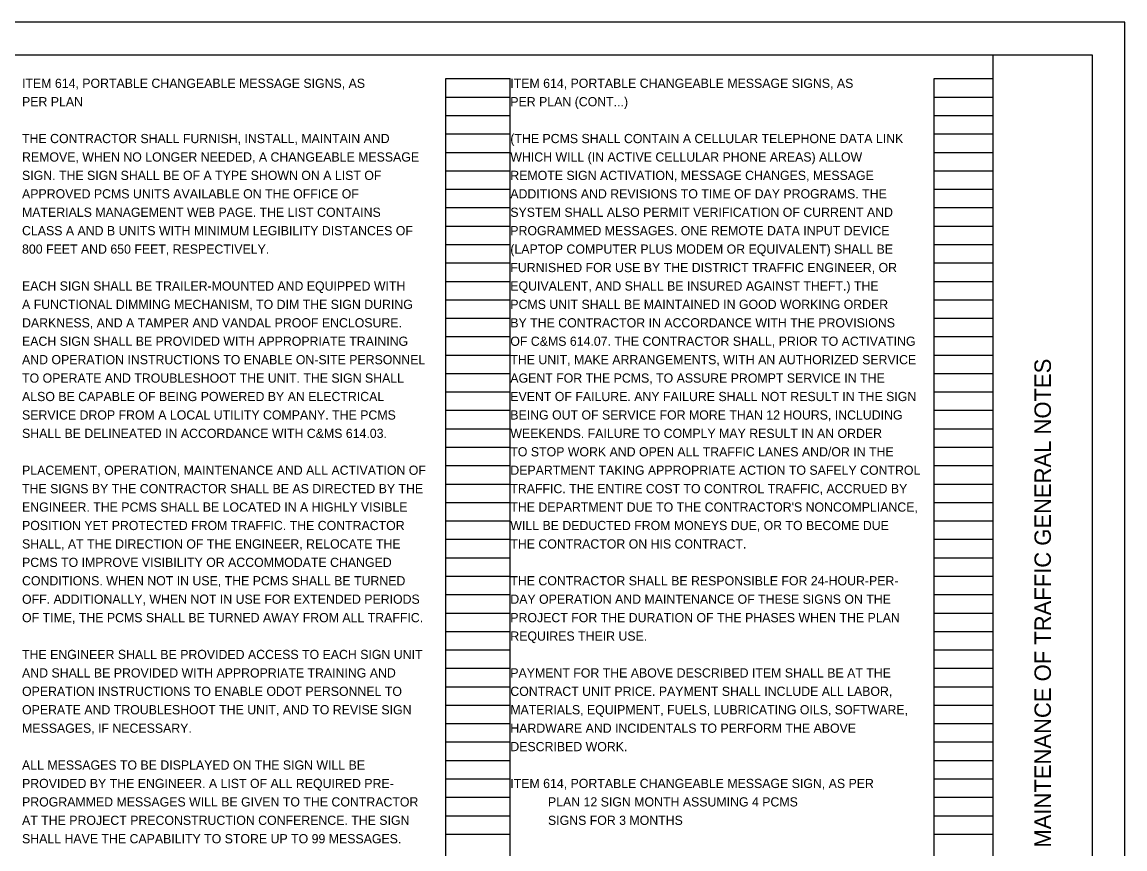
# Model space of a CAD drawing. Extents: x 0 to 34, y 0 to 22.
# Drawn here: x 17.24 to 34, y 9.43 to 22 of the extents above; entities that cross this region are included whole.
import ezdxf

# ---------------------------------------------------------------- set-up
doc = ezdxf.new("R2010")
doc.units = 0
for name, color, linetype in [('SH_Border', 7, 'Continuous'), ('SH_Cut_Line', 7, 'Continuous'), ('SH_Data', 7, 'Continuous'), ('SH_Text', 7, 'Continuous')]:
    doc.layers.add(name, color=color, linetype=linetype)

msp = doc.modelspace()

# ---------------------------------------------------------------- linework, layer by layer
at = {"layer": 'SH_Border'}
msp.add_line((32, 0.5), (32, 21.5), dxfattribs=at)
msp.add_lwpolyline([(1.5, 21.5), (33.5, 21.5), (33.5, 0.5), (1.5, 0.5)], close=True, dxfattribs=at)
at = {"layer": 'SH_Cut_Line'}
msp.add_lwpolyline([(0, 0), (34, 0), (34, 22), (0, 22)], close=True, dxfattribs=at)
at = {"layer": 'SH_Data'}
for p, q in [((23.68, 0.98), (23.68, 21.14)), ((23.68, 21.14), (24.66, 21.14)), ((24.66, 0.98), (24.66, 21.14)), ((31.1, 0.98), (31.1, 21.14)), ((31.1, 21.14), (32, 21.14)), ((32, 0.98), (32, 21.14)), ((23.68, 20.86), (24.66, 20.86)), ((31.1, 20.86), (32, 20.86)), ((23.68, 20.58), (24.66, 20.58)), ((31.1, 20.58), (32, 20.58)), ((23.68, 20.3), (24.66, 20.3)), ((31.1, 20.3), (32, 20.3)), ((23.68, 20.02), (24.66, 20.02)), ((31.1, 20.02), (32, 20.02)), ((23.68, 19.74), (24.66, 19.74)), ((31.1, 19.74), (32, 19.74)), ((23.68, 19.46), (24.66, 19.46)), ((31.1, 19.46), (32, 19.46)), ((23.68, 19.18), (24.66, 19.18)), ((31.1, 19.18), (32, 19.18)), ((23.68, 18.9), (24.66, 18.9)), ((31.1, 18.9), (32, 18.9)), ((23.68, 18.62), (24.66, 18.62)), ((31.1, 18.62), (32, 18.62)), ((23.68, 18.34), (24.66, 18.34)), ((31.1, 18.34), (32, 18.34)), ((23.68, 18.06), (24.66, 18.06)), ((31.1, 18.06), (32, 18.06)), ((23.68, 17.78), (24.66, 17.78)), ((31.1, 17.78), (32, 17.78)), ((23.68, 17.5), (24.66, 17.5)), ((31.1, 17.5), (32, 17.5)), ((23.68, 17.22), (24.66, 17.22)), ((31.1, 17.22), (32, 17.22)), ((23.68, 16.94), (24.66, 16.94)), ((31.1, 16.94), (32, 16.94)), ((23.68, 16.66), (24.66, 16.66)), ((31.1, 16.66), (32, 16.66)), ((23.68, 16.38), (24.66, 16.38)), ((31.1, 16.38), (32, 16.38)), ((23.68, 16.1), (24.66, 16.1)), ((31.1, 16.1), (32, 16.1)), ((23.68, 15.82), (24.66, 15.82)), ((31.1, 15.82), (32, 15.82)), ((23.68, 15.54), (24.66, 15.54)), ((31.1, 15.54), (32, 15.54)), ((23.68, 15.26), (24.66, 15.26)), ((31.1, 15.26), (32, 15.26)), ((23.68, 14.98), (24.66, 14.98)), ((31.1, 14.98), (32, 14.98)), ((23.68, 14.7), (24.66, 14.7)), ((31.1, 14.7), (32, 14.7)), ((23.68, 14.42), (24.66, 14.42)), ((31.1, 14.42), (32, 14.42)), ((23.68, 14.14), (24.66, 14.14)), ((31.1, 14.14), (32, 14.14)), ((23.68, 13.86), (24.66, 13.86)), ((31.1, 13.86), (32, 13.86)), ((23.68, 13.58), (24.66, 13.58)), ((31.1, 13.58), (32, 13.58)), ((23.68, 13.3), (24.66, 13.3)), ((31.1, 13.3), (32, 13.3)), ((23.68, 13.02), (24.66, 13.02)), ((31.1, 13.02), (32, 13.02)), ((23.68, 12.74), (24.66, 12.74)), ((31.1, 12.74), (32, 12.74)), ((23.68, 12.46), (24.66, 12.46)), ((31.1, 12.46), (32, 12.46)), ((23.68, 12.18), (24.66, 12.18)), ((31.1, 12.18), (32, 12.18)), ((23.68, 11.9), (24.66, 11.9)), ((31.1, 11.9), (32, 11.9)), ((23.68, 11.62), (24.66, 11.62)), ((31.1, 11.62), (32, 11.62)), ((23.68, 11.34), (24.66, 11.34)), ((31.1, 11.34), (32, 11.34)), ((23.68, 11.06), (24.66, 11.06)), ((31.1, 11.06), (32, 11.06)), ((23.68, 10.78), (24.66, 10.78)), ((31.1, 10.78), (32, 10.78)), ((23.68, 10.5), (24.66, 10.5)), ((31.1, 10.5), (32, 10.5)), ((23.68, 10.22), (24.66, 10.22)), ((31.1, 10.22), (32, 10.22)), ((23.68, 9.94), (24.66, 9.94)), ((31.1, 9.94), (32, 9.94)), ((23.68, 9.66), (24.66, 9.66)), ((31.1, 9.66), (32, 9.66))]:
    msp.add_line(p, q, dxfattribs=at)

# ---------------------------------------------------------------- texts
msp.add_text('MAINTENANCE OF TRAFFIC GENERAL NOTES', height=0.25, rotation=90, dxfattribs=at).set_placement((32.875, 9.455))
at = {"layer": 'SH_Text'}
for s, p in [('ITEM 614, PORTABLE CHANGEABLE MESSAGE SIGNS, AS', (17.24, 21)), ('ITEM 614, PORTABLE CHANGEABLE MESSAGE SIGNS, AS', (24.66, 21)), ('PER PLAN', (17.24, 20.72)), ('PER PLAN (CONT...)', (24.66, 20.72)), ('THE CONTRACTOR SHALL FURNISH, INSTALL, MAINTAIN AND', (17.24, 20.16)), ('(THE PCMS SHALL CONTAIN A CELLULAR TELEPHONE DATA LINK', (24.66, 20.16)), ('REMOVE, WHEN NO LONGER NEEDED, A CHANGEABLE MESSAGE', (17.24, 19.88)), ('WHICH WILL (IN ACTIVE CELLULAR PHONE AREAS) ALLOW', (24.66, 19.88)), ('SIGN. THE SIGN SHALL BE OF A TYPE SHOWN ON A LIST OF', (17.24, 19.6)), ('REMOTE SIGN ACTIVATION, MESSAGE CHANGES, MESSAGE', (24.66, 19.6)), ('APPROVED PCMS UNITS AVAILABLE ON THE OFFICE OF', (17.24, 19.32)), ('ADDITIONS AND REVISIONS TO TIME OF DAY PROGRAMS. THE', (24.66, 19.32)), ('MATERIALS MANAGEMENT WEB PAGE. THE LIST CONTAINS', (17.24, 19.04)), ('SYSTEM SHALL ALSO PERMIT VERIFICATION OF CURRENT AND', (24.66, 19.04)), ('CLASS A AND B UNITS WITH MINIMUM LEGIBILITY DISTANCES OF', (17.24, 18.76)), ('PROGRAMMED MESSAGES. ONE REMOTE DATA INPUT DEVICE', (24.66, 18.76)), ('800 FEET AND 650 FEET, RESPECTIVELY.', (17.24, 18.48)), ('(LAPTOP COMPUTER PLUS MODEM OR EQUIVALENT) SHALL BE', (24.66, 18.48)), ('FURNISHED FOR USE BY THE DISTRICT TRAFFIC ENGINEER, OR', (24.66, 18.2)), ('EACH SIGN SHALL BE TRAILER-MOUNTED AND EQUIPPED WITH', (17.24, 17.92)), ('EQUIVALENT, AND SHALL BE INSURED AGAINST THEFT.) THE', (24.66, 17.92)), ('A FUNCTIONAL DIMMING MECHANISM, TO DIM THE SIGN DURING', (17.24, 17.64)), ('PCMS UNIT SHALL BE MAINTAINED IN GOOD WORKING ORDER', (24.66, 17.64)), ('DARKNESS, AND A TAMPER AND VANDAL PROOF ENCLOSURE.', (17.24, 17.36)), ('BY THE CONTRACTOR IN ACCORDANCE WITH THE PROVISIONS', (24.66, 17.36)), ('EACH SIGN SHALL BE PROVIDED WITH APPROPRIATE TRAINING', (17.24, 17.08)), ('OF C&MS 614.07. THE CONTRACTOR SHALL, PRIOR TO ACTIVATING', (24.66, 17.08)), ('AND OPERATION INSTRUCTIONS TO ENABLE ON-SITE PERSONNEL', (17.24, 16.8)), ('THE UNIT, MAKE ARRANGEMENTS, WITH AN AUTHORIZED SERVICE', (24.66, 16.8)), ('TO OPERATE AND TROUBLESHOOT THE UNIT. THE SIGN SHALL', (17.24, 16.52)), ('AGENT FOR THE PCMS, TO ASSURE PROMPT SERVICE IN THE', (24.66, 16.52)), ('ALSO BE CAPABLE OF BEING POWERED BY AN ELECTRICAL', (17.24, 16.24)), ('EVENT OF FAILURE. ANY FAILURE SHALL NOT RESULT IN THE SIGN', (24.66, 16.24)), ('SERVICE DROP FROM A LOCAL UTILITY COMPANY. THE PCMS', (17.24, 15.96)), ('BEING OUT OF SERVICE FOR MORE THAN 12 HOURS, INCLUDING', (24.66, 15.96)), ('SHALL BE DELINEATED IN ACCORDANCE WITH C&MS 614.03.', (17.24, 15.68)), ('WEEKENDS. FAILURE TO COMPLY MAY RESULT IN AN ORDER', (24.66, 15.68)), ('TO STOP WORK AND OPEN ALL TRAFFIC LANES AND/OR IN THE', (24.66, 15.4)), ('PLACEMENT, OPERATION, MAINTENANCE AND ALL ACTIVATION OF', (17.24, 15.12)), ('DEPARTMENT TAKING APPROPRIATE ACTION TO SAFELY CONTROL', (24.66, 15.12)), ('THE SIGNS BY THE CONTRACTOR SHALL BE AS DIRECTED BY THE', (17.24, 14.84)), ('TRAFFIC. THE ENTIRE COST TO CONTROL TRAFFIC, ACCRUED BY', (24.66, 14.84)), ('ENGINEER. THE PCMS SHALL BE LOCATED IN A HIGHLY VISIBLE', (17.24, 14.56)), ("THE DEPARTMENT DUE TO THE CONTRACTOR'S NONCOMPLIANCE,", (24.66, 14.56)), ('POSITION YET PROTECTED FROM TRAFFIC. THE CONTRACTOR', (17.24, 14.28)), ('WILL BE DEDUCTED FROM MONEYS DUE, OR TO BECOME DUE', (24.66, 14.28)), ('SHALL, AT THE DIRECTION OF THE ENGINEER, RELOCATE THE', (17.24, 14)), ('THE CONTRACTOR ON HIS CONTRACT.', (24.66, 14)), ('PCMS TO IMPROVE VISIBILITY OR ACCOMMODATE CHANGED', (17.24, 13.72)), ('CONDITIONS. WHEN NOT IN USE, THE PCMS SHALL BE TURNED', (17.24, 13.44)), ('THE CONTRACTOR SHALL BE RESPONSIBLE FOR 24-HOUR-PER-', (24.66, 13.44)), ('OFF. ADDITIONALLY, WHEN NOT IN USE FOR EXTENDED PERIODS', (17.24, 13.16)), ('DAY OPERATION AND MAINTENANCE OF THESE SIGNS ON THE', (24.66, 13.16)), ('OF TIME, THE PCMS SHALL BE TURNED AWAY FROM ALL TRAFFIC.', (17.24, 12.88)), ('PROJECT FOR THE DURATION OF THE PHASES WHEN THE PLAN', (24.66, 12.88)), ('REQUIRES THEIR USE.', (24.66, 12.6)), ('THE ENGINEER SHALL BE PROVIDED ACCESS TO EACH SIGN UNIT', (17.24, 12.32)), ('AND SHALL BE PROVIDED WITH APPROPRIATE TRAINING AND', (17.24, 12.04)), ('PAYMENT FOR THE ABOVE DESCRIBED ITEM SHALL BE AT THE', (24.66, 12.04)), ('OPERATION INSTRUCTIONS TO ENABLE ODOT PERSONNEL TO', (17.24, 11.76)), ('CONTRACT UNIT PRICE. PAYMENT SHALL INCLUDE ALL LABOR,', (24.66, 11.76)), ('OPERATE AND TROUBLESHOOT THE UNIT, AND TO REVISE SIGN', (17.24, 11.48)), ('MATERIALS, EQUIPMENT, FUELS, LUBRICATING OILS, SOFTWARE,', (24.66, 11.48)), ('MESSAGES, IF NECESSARY.', (17.24, 11.2)), ('HARDWARE AND INCIDENTALS TO PERFORM THE ABOVE', (24.66, 11.2)), ('DESCRIBED WORK.', (24.66, 10.92)), ('ALL MESSAGES TO BE DISPLAYED ON THE SIGN WILL BE', (17.24, 10.64)), ('PROVIDED BY THE ENGINEER. A LIST OF ALL REQUIRED PRE-', (17.24, 10.36)), ('ITEM 614, PORTABLE CHANGEABLE MESSAGE SIGN, AS PER', (24.66, 10.36)), ('PROGRAMMED MESSAGES WILL BE GIVEN TO THE CONTRACTOR', (17.24, 10.08)), ('           PLAN 12 SIGN MONTH ASSUMING 4 PCMS', (24.66, 10.08)), ('AT THE PROJECT PRECONSTRUCTION CONFERENCE. THE SIGN', (17.24, 9.8)), ('           SIGNS FOR 3 MONTHS', (24.66, 9.8)), ('SHALL HAVE THE CAPABILITY TO STORE UP TO 99 MESSAGES.', (17.24, 9.52))]:
    msp.add_text(s, height=0.14, dxfattribs=at).set_placement(p)

doc.saveas('drawing.dxf')
